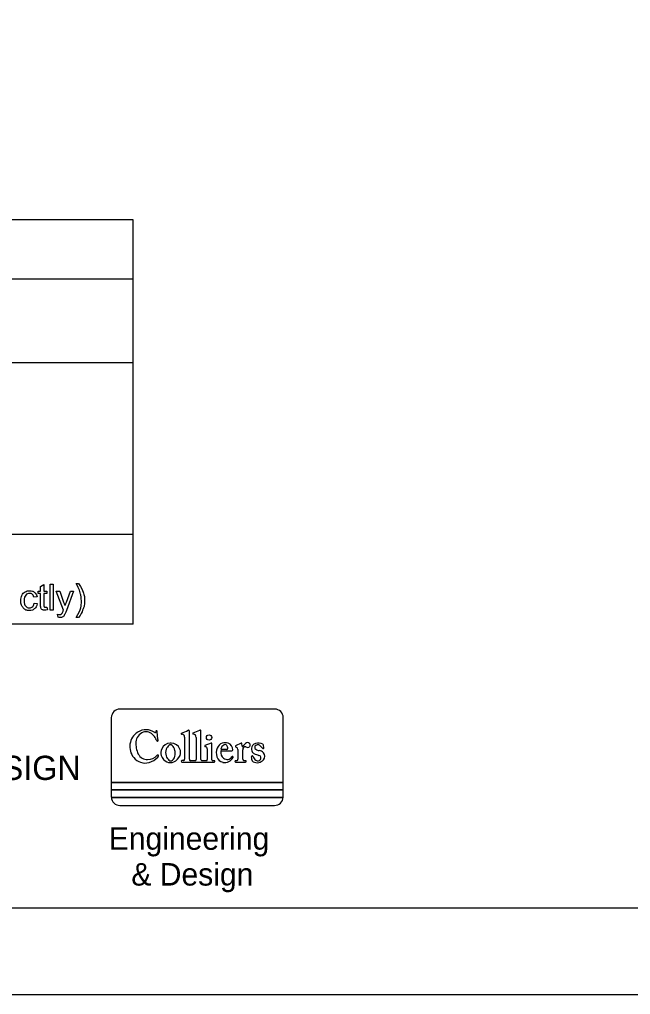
# Model space of a CAD drawing. Extents: x 0 to 39.4, y 0 to 22.
# Drawn here: x 5.97 to 9.51, y 0 to 5.64 of the extents above; entities that cross this region are included whole.
import ezdxf

# ---------------------------------------------------------------- set-up
doc = ezdxf.new("R2010")
doc.units = 0
for name, color, linetype in [('SH_Border', 7, 'Continuous'), ('SH_Cut_Line', 7, 'Continuous'), ('SH_Data', 7, 'Continuous'), ('SH_Text', 7, 'Continuous')]:
    doc.layers.add(name, color=color, linetype=linetype)

msp = doc.modelspace()

# ---------------------------------------------------------------- linework, layer by layer
at = {"layer": 'SH_Border'}
msp.add_lwpolyline([(1.5, 21.5), (33.5, 21.5), (33.5, 0.5), (1.5, 0.5)], close=True, dxfattribs=at)
at = {"layer": 'SH_Cut_Line'}
msp.add_lwpolyline([(0, 0), (34, 0), (34, 22), (0, 22)], close=True, dxfattribs=at)
at = {"layer": 'SH_Data'}
for p, q in [((6.6275, 4.4803), (2.3775, 4.4803)), ((6.6275, 2.1428), (6.6275, 4.4803)), ((2.3775, 4.1387), (6.6275, 4.1387)), ((2.3775, 3.6553), (6.6275, 3.6553)), ((6.6275, 2.6607), (2.3775, 2.6607)), ((6.6275, 2.1428), (2.3775, 2.1428))]:
    msp.add_line(p, q, dxfattribs=at)
at = {"layer": 'SH_Text'}
for p, q in [((7.4469, 1.6508), (6.5513, 1.6508)), ((6.9533, 1.3603), (6.9533, 1.5241)), ((7.0202, 1.359), (7.0202, 1.5242)), ((6.7586, 1.5213), (6.7588, 1.5182)), ((6.7631, 1.4721), (6.765, 1.4672)), ((6.9259, 1.489), (6.9259, 1.3609)), ((6.993, 1.4873), (6.993, 1.3593)), ((6.8478, 1.4535), (6.8422, 1.4535)), ((7.0796, 1.4543), (7.0434, 1.4402)), ((7.0568, 1.4203), (7.0568, 1.3589)), ((7.084, 1.3573), (7.084, 1.4511)), ((7.1711, 1.4178), (7.1397, 1.4178)), ((7.2527, 1.4542), (7.2211, 1.4387)), ((7.2213, 1.4328), (7.2278, 1.4292)), ((7.2346, 1.4174), (7.2346, 1.3606)), ((7.2595, 1.4359), (7.258, 1.4512)), ((7.262, 1.3604), (7.262, 1.4147)), ((7.3619, 1.4407), (7.3769, 1.4243)), ((7.3846, 1.4277), (7.3821, 1.4427)), ((6.7699, 1.373), (6.774, 1.3776)), ((7.1385, 1.4098), (7.1989, 1.4098)), ((6.919, 1.353), (6.9098, 1.353)), ((6.9098, 1.3448), (7.0973, 1.3448)), ((6.9865, 1.3524), (6.9595, 1.3524)), ((7.0516, 1.3524), (7.0261, 1.3524)), ((7.0973, 1.3524), (7.0886, 1.3524)), ((7.2276, 1.3524), (7.2206, 1.3524)), ((7.2207, 1.3448), (7.2786, 1.3448)), ((7.2786, 1.3524), (7.2691, 1.3524)), ((6.5016, 1.1404), (7.4966, 1.1404)), ((7.4966, 1.1404), (6.5016, 1.1404)), ((7.4967, 1.1432), (7.4967, 1.1829)), ((6.5513, 1.0934), (7.4469, 1.0934))]:
    msp.add_line(p, q, dxfattribs=at)
for points in [[(6.092, 2.2558), (6.092, 2.3185), (6.0784, 2.3185), (6.0784, 2.3328), (6.092, 2.3328), (6.092, 2.3597), (6.1105, 2.3708), (6.1105, 2.3328), (6.1289, 2.3328), (6.1289, 2.3185), (6.1105, 2.3185), (6.1105, 2.2547)], [(6.1465, 2.2239), (6.1465, 2.3741), (6.1649, 2.3741), (6.1649, 2.2239), (6.1465, 2.2239)], [(6.2974, 2.3766), (6.3105, 2.3766)], [(6.2243, 2.2238), (6.183, 2.3328), (6.2029, 2.3328), (6.2255, 2.2699)], [(6.241, 2.2693), (6.2643, 2.3328), (6.2827, 2.3328), (6.2414, 2.222)], [(6.0712, 2.3007), (6.0532, 2.298)], [(6.0548, 2.2638), (6.0729, 2.2613)], [(6.1289, 2.2404), (6.1315, 2.2241)], [(6.1928, 2.1821), (6.1907, 2.1995)], [(6.3105, 2.1798), (6.2974, 2.1798)], [(6.5015, 1.601), (6.5015, 1.2253), (7.4967, 1.2253), (7.4967, 1.601)], [(6.7729, 1.4691), (6.7682, 1.4941), (6.7664, 1.5223)], [(7.4967, 1.1829), (6.5015, 1.1829), (6.5015, 1.1432)]]:
    msp.add_lwpolyline(points, dxfattribs=at)
msp.add_lwpolyline([(7.4967, 1.2253), (6.5015, 1.2253), (6.5015, 1.1829), (7.4967, 1.1829)], close=True, dxfattribs=at)
msp.add_circle((7.0672, 1.4866), 0.0155, dxfattribs=at)
for centre, radius, start, end in [((6.5513, 1.601), 0.0498, 90, 180), ((7.4469, 1.601), 0.0498, 0, 90), ((6.7018, 1.4429), 0.0884, 54.7696, 122.7772), ((6.7625, 1.5215), 0.00392, 10.93, 183.8175), ((6.7963, 1.8292), 0.3364, 289.2258, 296.5694), ((6.9486, 1.524), 0.00466, 0.7043, 112.8976), ((6.8934, 1.7763), 0.2752, 287.2899, 295.7863), ((7.0152, 1.5239), 0.00504, 3.9002, 114.2106), ((6.7079, 1.4334), 0.0996, 122.7772, 219.4331), ((6.7089, 1.4562), 0.0652, 110.6135, 175.9543), ((6.7019, 1.4748), 0.0454, 67.8997, 110.6135), ((6.6892, 1.4433), 0.0794, 21.2674, 67.8997), ((6.755, 1.5182), 0.00381, 234.7696, 0.2433), ((6.7686, 1.4695), 0.00427, 213.048, 354.7379), ((6.9088, 1.5088), 0.00323, 122.5943, 271.3615), ((6.9093, 1.489), 0.0166, 0, 91.3615), ((6.9764, 1.5099), 0.00377, 108.5217, 257.147), ((6.9739, 1.4873), 0.019, 0, 85.065), ((6.7783, 1.4513), 0.1348, 175.9543, 206.5569), ((6.8458, 1.3976), 0.0573, 155.0154, 195.9836), ((6.8436, 1.3986), 0.0549, 91.4708, 155.0154), ((6.8788, 1.3982), 0.0628, 159.8672, 197.1421), ((6.8654, 1.4031), 0.0485, 128.4847, 159.8672), ((6.8441, 1.4299), 0.0143, 51.5153, 128.4847), ((6.8478, 1.3989), 0.0547, 22.5432, 90), ((6.8245, 1.4053), 0.0457, 8.6045, 51.5153), ((6.7842, 1.3953), 0.0872, 354.2931, 11.1311), ((6.8514, 1.4004), 0.0508, 340.2533, 22.5432), ((7.0458, 1.437), 0.00399, 126.9098, 263.7558), ((7.044, 1.4203), 0.0128, 0, 83.7558), ((7.0808, 1.4513), 0.00324, 356.2318, 111.3032), ((7.1879, 1.3972), 0.0786, 158.9201, 196.7689), ((7.1581, 1.4087), 0.0468, 107.3884, 158.9201), ((7.1397, 1.4212), 0.00338, 167.2691, 270), ((7.1688, 1.4146), 0.0332, 120.4846, 167.2691), ((7.1608, 1.4001), 0.0557, 72.6116, 107.3884), ((7.1593, 1.4309), 0.0144, 42.3189, 120.4846), ((7.1528, 1.425), 0.0231, 354.1231, 42.3189), ((7.1704, 1.4232), 0.00543, 277.2594, 354.1231), ((7.1661, 1.4169), 0.0381, 357.2625, 72.6116), ((7.1986, 1.4153), 0.00555, 272.7564, 357.2625), ((7.2229, 1.4358), 0.0034, 121.2415, 241.2505), ((7.2209, 1.4174), 0.0136, 0, 59.7444), ((7.2543, 1.4508), 0.00375, 6.4513, 116.174), ((7.261, 1.436), 0.00158, 185.3907, 323.4477), ((7.2855, 1.4147), 0.0235, 141.4263, 180.0327), ((7.3459, 1.3731), 0.104, 130.2856, 143.4477), ((7.2754, 1.4228), 0.0105, 58.8554, 141.4263), ((7.2902, 1.4388), 0.0179, 49.7144, 130.2856), ((7.2901, 1.4472), 0.018, 238.8554, 310.2856), ((7.2937, 1.443), 0.0124, 310.2856, 49.7144), ((7.3455, 1.4201), 0.0332, 143.4089, 199.3264), ((7.3457, 1.42), 0.0334, 105.6066, 143.4089), ((7.345, 1.4296), 0.0133, 123.6114, 236.3886), ((7.3517, 1.3984), 0.0558, 61.5074, 105.6066), ((7.3509, 1.4208), 0.0238, 78.1441, 123.6114), ((7.3636, 1.4576), 0.0468, 236.3886, 262.0524), ((7.3534, 1.4329), 0.0115, 42.5173, 78.1441), ((7.3515, 1.3709), 0.0407, 40.9976, 82.0524), ((7.3803, 1.4271), 0.00433, 219.7222, 9.1323), ((7.3745, 1.4404), 0.00795, 16.8946, 61.5074), ((6.6972, 1.4246), 0.0857, 219.4331, 285.3506), ((6.7105, 1.4174), 0.059, 206.5569, 271.2175), ((6.7101, 1.4357), 0.0773, 271.2175, 317.7042), ((6.6923, 1.4421), 0.1039, 285.3506, 318.3029), ((6.7706, 1.3807), 0.00456, 317.5815, 137.7042), ((6.8454, 1.3975), 0.0568, 195.9836, 247.4134), ((6.8691, 1.3953), 0.0527, 197.1421, 229.9048), ((6.8453, 1.367), 0.0157, 229.9048, 310.0952), ((6.8247, 1.3896), 0.0463, 311.5123, 356.3189), ((6.8378, 1.4052), 0.0652, 292.5866, 340.2533), ((6.919, 1.36), 0.00695, 270, 7.6881), ((6.9613, 1.3603), 0.00806, 180, 256.9766), ((6.9865, 1.3589), 0.0065, 270, 3.1556), ((7.0267, 1.3589), 0.00652, 179.2506, 264.6402), ((7.0516, 1.3577), 0.00532, 270, 12.3402), ((7.0889, 1.3573), 0.00485, 180, 266.7746), ((7.1562, 1.3877), 0.0455, 196.7689, 259.4625), ((7.1806, 1.4023), 0.0459, 174.8749, 230.9242), ((7.1385, 1.4061), 0.00367, 90, 174.8749), ((7.1581, 1.3982), 0.0563, 259.4625, 329.9587), ((7.1719, 1.3916), 0.0321, 230.9242, 328.1623), ((7.2029, 1.3723), 0.00454, 329.9587, 148.1623), ((7.2276, 1.3595), 0.00704, 270, 9.7141), ((7.27, 1.3603), 0.00796, 179.3196, 263.9925), ((7.3175, 1.3755), 0.00485, 20.4198, 193.2731), ((7.2003, 1.3478), 0.1156, 4.8826, 13.2731), ((7.339, 1.4178), 0.0263, 199.3264, 242.7351), ((7.3295, 1.3589), 0.014, 184.8826, 242.2064), ((7.3705, 1.3952), 0.0516, 200.4198, 231.7135), ((7.3456, 1.3894), 0.0486, 242.2064, 319.0024), ((7.3931, 1.5229), 0.1445, 242.7351, 255.1442), ((7.3499, 1.3692), 0.0185, 231.7135, 325.4966), ((7.352, 1.3678), 0.016, 325.4966, 75.1442), ((7.3592, 1.3776), 0.0305, 319.0024, 40.9976), ((6.8432, 1.3923), 0.0512, 247.4134, 292.5866), ((6.9098, 1.3489), 0.00412, 90, 270), ((7.0973, 1.3486), 0.00381, 270, 90), ((7.2207, 1.3486), 0.00381, 91.0116, 270), ((7.2786, 1.3486), 0.00381, 270, 90), ((6.5513, 1.1432), 0.0498, 180, 183.1495), ((6.5513, 1.1432), 0.0498, 183.1495, 270), ((7.4469, 1.1432), 0.0498, 270, 356.8505), ((7.4469, 1.1432), 0.0498, 356.8505, 0)]:
    msp.add_arc(centre, radius, start, end, dxfattribs=at)
for points in [[(6.2974, 2.1798), (6.3279, 2.2289), (6.3279, 2.2782), (6.3279, 2.2974), (6.3235, 2.3164), (6.32, 2.3317), (6.3138, 2.3459), (6.3098, 2.3551), (6.2974, 2.3766)], [(6.3105, 2.3766), (6.3298, 2.3509), (6.339, 2.325), (6.3469, 2.3026), (6.3469, 2.2783), (6.3469, 2.2506), (6.3363, 2.2248), (6.3257, 2.199), (6.3105, 2.1798)], [(6.0729, 2.2613), (6.07, 2.2427), (6.0577, 2.2321), (6.0455, 2.2215), (6.0277, 2.2215), (6.0053, 2.2215), (5.9917, 2.2361), (5.9782, 2.2507), (5.9782, 2.2779), (5.9782, 2.2955), (5.984, 2.3088), (5.9899, 2.322), (6.0018, 2.3286), (6.0137, 2.3352), (6.0278, 2.3352), (6.0455, 2.3352), (6.0568, 2.3262), (6.068, 2.3172), (6.0712, 2.3007)], [(6.0532, 2.298), (6.0507, 2.309), (6.0442, 2.3145), (6.0377, 2.3201), (6.0285, 2.3201), (6.0146, 2.3201), (6.0059, 2.3101), (5.9972, 2.3001), (5.9972, 2.2784), (5.9972, 2.2565), (6.0056, 2.2466), (6.014, 2.2366), (6.0275, 2.2366), (6.0384, 2.2366), (6.0456, 2.2433), (6.0529, 2.2499), (6.0548, 2.2638)], [(6.2255, 2.2699), (6.2299, 2.258), (6.2334, 2.2448), (6.2366, 2.2572), (6.241, 2.2693)], [(6.1315, 2.2241), (6.1238, 2.2224), (6.1176, 2.2224), (6.1076, 2.2224), (6.1021, 2.2256), (6.0965, 2.2288), (6.0943, 2.234), (6.092, 2.2392), (6.092, 2.2558)], [(6.1105, 2.2547), (6.1105, 2.2468), (6.1114, 2.2445), (6.1124, 2.2423), (6.1146, 2.2409), (6.1168, 2.2396), (6.1209, 2.2396), (6.1239, 2.2396), (6.1289, 2.2404)], [(6.1907, 2.1995), (6.1967, 2.1978), (6.2012, 2.1978), (6.2074, 2.1978), (6.211, 2.1999), (6.2147, 2.2019), (6.2171, 2.2056), (6.2188, 2.2084), (6.2227, 2.2193), (6.2232, 2.2209), (6.2243, 2.2238)], [(6.2414, 2.222), (6.2348, 2.2042), (6.2311, 2.1974), (6.2262, 2.1883), (6.2198, 2.1841), (6.2135, 2.1799), (6.2046, 2.1799), (6.1993, 2.1799), (6.1928, 2.1821)]]:
    msp.add_open_spline(points, degree=3, dxfattribs=at)

# ---------------------------------------------------------------- texts
for s, height, p in [('COLLIERS ENGINEERING AND DESIGN', 0.14, (2.8185, 1.241)), ('Engineering', 0.130253, (6.4864, 0.8371)), ('& Design', 0.13025, (6.6172, 0.6301))]:
    msp.add_text(s, height=height, dxfattribs=at).set_placement(p)

doc.saveas('drawing.dxf')
